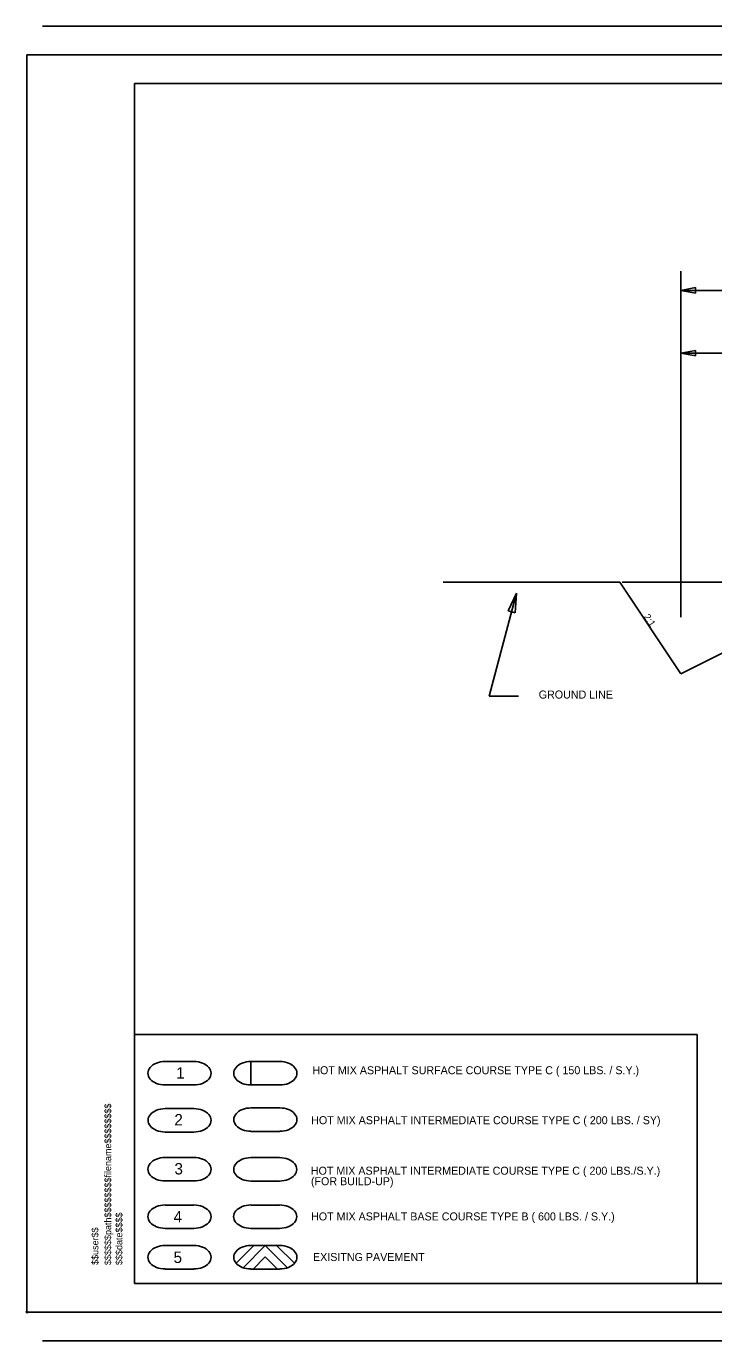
# Model space of a CAD drawing. Extents: x -9123 to -7163, y 44168 to 46468.
# Drawn here: x -8960 to -8358, y 44168 to 45318 of the extents above; entities that cross this region are included whole.
import ezdxf

# ---------------------------------------------------------------- set-up
doc = ezdxf.new("R2010")
doc.units = 0
for name, color, linetype in [('RD_SHT_Bndy', 7, 'Continuous'), ('RD_SHT_ID', 7, 'Continuous'), ('RD_SHT_IplotShp', 7, 'Continuous'), ('RD_SHT_Snap', 7, 'Continuous'), ('RD_TX_TypSect', 7, 'Continuous'), ('RD_XS_PaveOvlay', 7, 'Continuous')]:
    doc.layers.add(name, color=color, linetype=linetype)

msp = doc.modelspace()

# ---------------------------------------------------------------- linework, layer by layer
at = {"layer": 'RD_SHT_Bndy'}
for p, q in [((-8945.7, 45318), (-7185.7, 45318)), ((-8945.7, 45318), (-7185.7, 45318)), ((-8945.7, 45293), (-7185.7, 45293)), ((-7190.2, 45268), (-8865.2, 45268)), ((-8865.2, 45268), (-8865.2, 44218)), ((-8865.2, 44218), (-7190.2, 44218)), ((-8945.7, 44193), (-7185.7, 44193)), ((-8945.7, 44168), (-7185.7, 44168))]:
    msp.add_line(p, q, dxfattribs=at)
at = {"layer": 'RD_SHT_IplotShp'}
msp.add_lwpolyline([(-8959.2, 45293), (-7163.2, 45293), (-7163.2, 44193), (-8959.2, 44193)], close=True, dxfattribs=at)
at = {"layer": 'RD_SHT_Snap'}
msp.add_line((-8959.2, 45293), (-8959.2, 44193), dxfattribs=at)
msp.add_circle((-8959.2, 44193), 0.607, dxfattribs=at)
at = {"layer": 'RD_TX_TypSect'}
for p, q in [((-8386.7, 44801), (-8386.7, 45103.7)), ((-8374, 45089.3), (-8386.7, 45086.9)), ((-8386.7, 45086.9), (-8003.3, 45086.9)), ((-8386.7, 45086.9), (-8374, 45084.6)), ((-8374, 45084.6), (-8374, 45089.3)), ((-8374, 45034.3), (-8386.7, 45031.9)), ((-8374, 45029.6), (-8374, 45034.3)), ((-8386.7, 45031.9), (-8374, 45029.6)), ((-8386.7, 45031.9), (-8286.7, 45031.9)), ((-8594.9, 44831.6), (-8440.8, 44831.6)), ((-8550.9, 44831.6), (-8440.1, 44831.6)), ((-8386.7, 44751.5), (-8440.1, 44831.6)), ((-8438.1, 44831.6), (-8110.1, 44831.6)), ((-8554.7, 44732), (-8530.7, 44822)), ((-8537.9, 44806.4), (-8530.7, 44822)), ((-8530.7, 44822), (-8531.8, 44804.8)), ((-8531.8, 44804.8), (-8537.9, 44806.4)), ((-8286.7, 44801.5), (-8386.7, 44751.5)), ((-8554.7, 44732), (-8529, 44732)), ((-8838.3, 44412.2), (-8813.1, 44412.2)), ((-8763.2, 44412.2), (-8737.9, 44412.2)), ((-8763.2, 44412.2), (-8763.2, 44391.7)), ((-8737.9, 44412.2), (-8763.2, 44412.2)), ((-8763.2, 44412.2), (-8763.2, 44391.7)), ((-8813.1, 44391.7), (-8838.3, 44391.7)), ((-8737.9, 44391.7), (-8763.2, 44391.7)), ((-8763.2, 44391.7), (-8737.9, 44391.7)), ((-8838.2, 44371.1), (-8813, 44371.1)), ((-8763.1, 44371.7), (-8737.9, 44371.7)), ((-8813, 44350.5), (-8838.2, 44350.5)), ((-8737.9, 44351.1), (-8763.1, 44351.1)), ((-8838.3, 44328.3), (-8813, 44328.3)), ((-8763.2, 44328.2), (-8738, 44328.2)), ((-8813, 44307.8), (-8838.3, 44307.8)), ((-8738, 44307.7), (-8763.2, 44307.7)), ((-8838.3, 44286.7), (-8813.1, 44286.7)), ((-8763.3, 44286.7), (-8738, 44286.7)), ((-8732.3, 44286), (-8732.4, 44286.2)), ((-8813.1, 44266.2), (-8838.3, 44266.2)), ((-8738, 44266.2), (-8763.3, 44266.2)), ((-8838.3, 44251.3), (-8813, 44251.3)), ((-8776, 44235.7), (-8760.5, 44251.3)), ((-8770, 44231.8), (-8750.6, 44251.3)), ((-8763.2, 44251.3), (-8737.9, 44251.3)), ((-8761.2, 44230.7), (-8750.6, 44241.4)), ((-8731.1, 44231.8), (-8750.6, 44251.3)), ((-8739.9, 44230.7), (-8750.6, 44241.4)), ((-8725.1, 44235.7), (-8740.7, 44251.3)), ((-8733.4, 44250.6), (-8733.4, 44250.8)), ((-8813, 44230.7), (-8838.3, 44230.7)), ((-8737.9, 44230.7), (-8763.2, 44230.7)), ((-8722.9, 44240.2), (-8723, 44240.3))]:
    msp.add_line(p, q, dxfattribs=at)
msp.add_lwpolyline([(-8865.2, 44218), (-8372.6, 44218), (-8372.6, 44435.8), (-8865.2, 44435.8)], close=True, dxfattribs=at)
for points in [[(-8737.9, 44371.7), (-8763.1, 44371.7)], [(-8763.1, 44351.1), (-8737.9, 44351.1)], [(-8738, 44328.2), (-8763.2, 44328.2)], [(-8763.2, 44307.7), (-8738, 44307.7)], [(-8739.5, 44286.5), (-8739.6, 44286.7)], [(-8739.4, 44286.7), (-8739.5, 44286.5)], [(-8740.5, 44251), (-8740.6, 44251.3)], [(-8740.4, 44251.3), (-8740.5, 44251)]]:
    msp.add_lwpolyline(points, dxfattribs=at)
for centre, start_param, end_param in [((-8838.3, 44402), 1.570796, 4.712389), ((-8813.1, 44402), 4.712389, 7.853982), ((-8763.2, 44402), 1.570796, 4.712389), ((-8763.2, 44402), 1.570796, 4.712389), ((-8737.9, 44402), 4.712389, 7.853982), ((-8737.9, 44402), 4.712389, 7.853982), ((-8838.2, 44360.8), 1.570796, 4.712389), ((-8813, 44360.8), 4.712389, 7.853982), ((-8763.1, 44361.4), 1.570796, 4.712389), ((-8763.1, 44361.4), 1.570796, 4.712389), ((-8737.9, 44361.4), 4.712389, 7.853982), ((-8737.9, 44361.4), 4.712389, 7.853982), ((-8838.3, 44318), 1.570796, 4.712389), ((-8813, 44318), 4.712389, 7.853982), ((-8763.2, 44317.9), 1.570796, 4.712389), ((-8763.2, 44317.9), 1.570796, 4.712389), ((-8738, 44317.9), 4.712389, 7.853982), ((-8738, 44317.9), 4.712389, 7.853982), ((-8838.3, 44276.5), 1.570796, 4.712389), ((-8813.1, 44276.5), 4.712389, 7.853982), ((-8763.3, 44276.5), 1.570796, 4.712389), ((-8738, 44276.5), 4.712389, 7.853982), ((-8838.3, 44241), 1.570796, 4.712389), ((-8813, 44241), 4.712389, 7.853982), ((-8763.2, 44241), 1.570796, 4.712389), ((-8737.9, 44241), 4.712389, 7.853982)]:
    msp.add_ellipse(centre, major_axis=(15, 0), ratio=0.682631, start_param=start_param, end_param=end_param, dxfattribs=at)
at = {"layer": 'RD_XS_PaveOvlay'}
for p, q in [((-8738, 44286.7), (-8763.3, 44286.7)), ((-8763.3, 44266.2), (-8738, 44266.2))]:
    msp.add_line(p, q, dxfattribs=at)
for centre, start_param, end_param in [((-8763.3, 44276.5), 1.570796, 4.712389), ((-8738, 44276.5), 4.712389, 7.853982)]:
    msp.add_ellipse(centre, major_axis=(15, 0), ratio=0.682631, start_param=start_param, end_param=end_param, dxfattribs=at)

# ---------------------------------------------------------------- texts
at = {"layer": 'RD_SHT_ID'}
for s, p in [('$$$$$$path$$$$$$$$filename$$$$$$$$', (-8885.5, 44234.2)), ('$$$date$$$$', (-8875.7, 44234.2)), ('$$user$$', (-8896.7, 44234.3))]:
    msp.add_text(s, height=5.88, rotation=90, dxfattribs=at).set_placement(p)
at = {"layer": 'RD_TX_TypSect'}
msp.add_text('2:1', height=6, rotation=304.1064, dxfattribs=at).set_placement((-8419.6, 44801.3))
for s, height, p in [('GROUND LINE', 7, (-8511.2, 44729.8)), ('1', 10, (-8828.6, 44397.2)), ('HOT MIX ASPHALT SURFACE COURSE TYPE C ( 150 LBS. / S.Y.)', 7, (-8709.4, 44401.1)), ('2', 10, (-8830.2, 44356.3)), ('HOT MIX ASPHALT INTERMEDIATE COURSE TYPE C ( 200 LBS. / SY)', 7, (-8710.4, 44357.4)), ('3', 10, (-8830.1, 44313.4)), ('(FOR BUILD-UP)', 7, (-8710.6, 44304)), ('HOT MIX ASPHALT INTERMEDIATE COURSE TYPE C ( 200 LBS./S.Y.)', 7, (-8710.7, 44313.2)), ('4', 10, (-8830.9, 44271.4)), ('HOT MIX ASPHALT BASE COURSE TYPE B ( 600 LBS. / S.Y.)', 7, (-8710.5, 44273.2)), ('5', 10, (-8830.9, 44236)), ('EXISITNG PAVEMENT', 7, (-8708.8, 44237.7))]:
    msp.add_text(s, height=height, dxfattribs=at).set_placement(p)

doc.saveas('drawing.dxf')
